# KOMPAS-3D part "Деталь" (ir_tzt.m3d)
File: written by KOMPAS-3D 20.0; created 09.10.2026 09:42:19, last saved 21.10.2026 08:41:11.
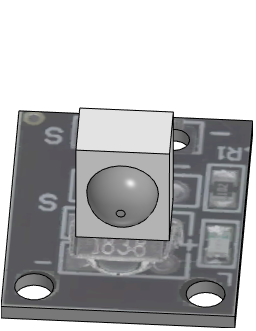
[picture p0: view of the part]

Document properties: Полное имя файла: D:\RicWork\Project-EPS32\box_compas\IR\ir_tzt.m3d

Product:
- Part/product: Деталь
    Масса: 0.00363733

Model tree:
1. Эскиз:1
2. Элемент выдавливания:1
     Расстояние 1 = 1
3. Эскиз:2  (with: Элемент выдавливания:1)
4. Элемент выдавливания:3
     Расстояние 2 = 1
5. Эскиз:3  (with: Элемент выдавливания:1)
6. Элемент выдавливания:4
     Расстояние 2 = 1
7. Массив по сетке:1  (with: Элемент выдавливания:4, Эскиз:3)  (3 pattern instances)
     Шаг 1 = 2.54; Угол раствора = 90
8. Эскиз:4  (with: Элемент выдавливания:1)
9. Элемент выдавливания:5
     Расстояние 1 = 9.5
10. Эскиз:5  (with: Элемент выдавливания:5)
11. Элемент выдавливания:6
     Расстояние 2 = 13.8939
12. Эскиз:6  (with: Элемент выдавливания:5)
13. Элемент выдавливания:7
     Расстояние 1 = 2
14. Скругление:1  (with: Элемент выдавливания:7)
     Радиус = 2

Referenced files in D:\myProjects\Progect_esp32\box_compas\: ir_tzt.png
